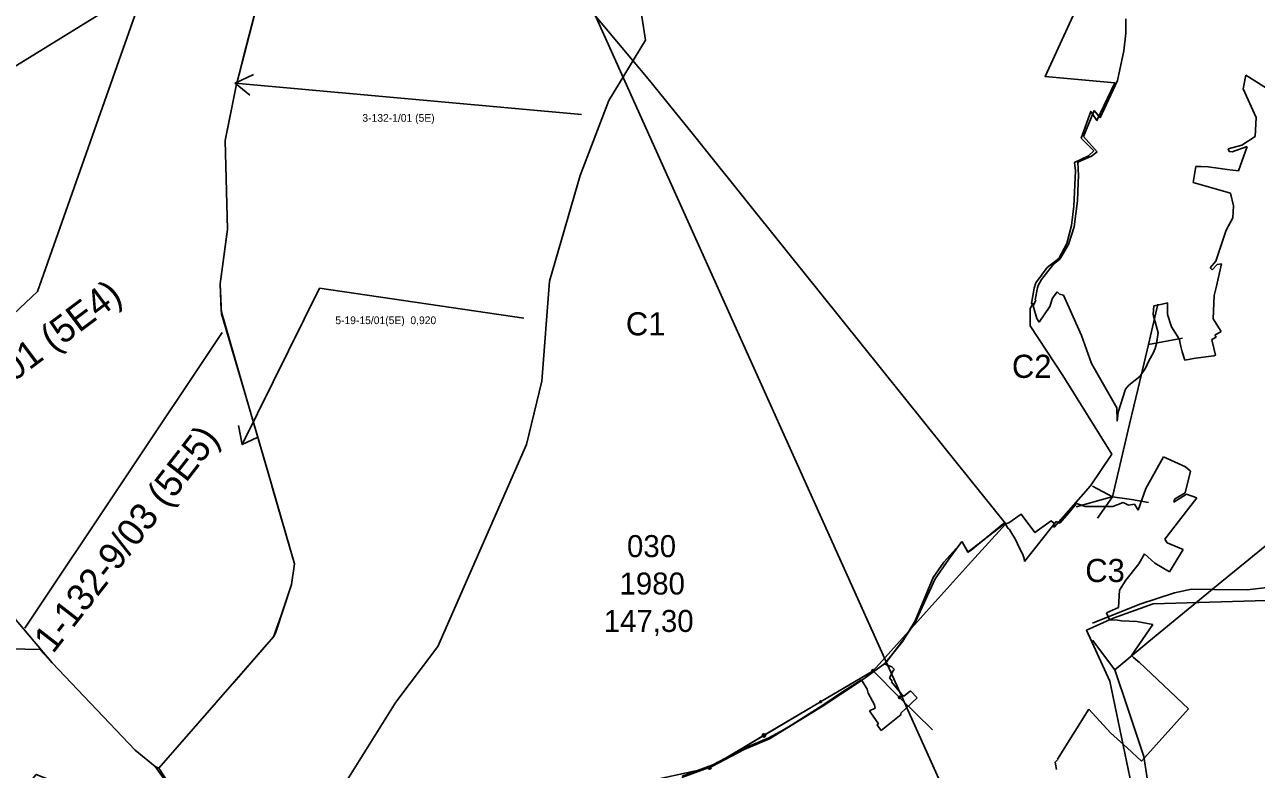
# Model space of a CAD drawing. Extents: x -557103 to -548162, y -1041918 to -1033974.
# Drawn here: x -553807 to -552210, y -1036489 to -1035524 of the extents above; entities that cross this region are included whole.
import ezdxf

# ---------------------------------------------------------------- set-up
doc = ezdxf.new("R2010")
doc.units = 0
for name, color, linetype in [('body3', 7, 'Continuous'), ('Vrstva 11', 7, 'Continuous'), ('Vrstva 12', 7, 'Continuous'), ('Vrstva 13', 7, 'Continuous'), ('Vrstva 14', 7, 'Continuous'), ('Vrstva 15', 7, 'Continuous'), ('Vrstva 16', 7, 'Continuous'), ('Vrstva 37', 7, 'Continuous'), ('Vrstva 49', 7, 'Continuous'), ('Vrstva 9', 7, 'Continuous')]:
    doc.layers.add(name, color=color, linetype=linetype)

msp = doc.modelspace()

# ---------------------------------------------------------------- linework, layer by layer
at = {"layer": 'body3'}
for p, q in [((-553499.5, -1035473.7), (-553532.1, -1035599.9)), ((-552379.3, -1035535), (-552379.4, -1035516.6)), ((-552382.1, -1035557.9), (-552379.3, -1035535)), ((-552383, -1035564), (-552382.1, -1035557.9)), ((-552390.2, -1035596.4), (-552383, -1035564)), ((-552223.9, -1035589.2), (-552227.3, -1035607.2)), ((-552104, -1035665.4), (-552223.9, -1035589.2)), ((-553533.5, -1035605.6), (-553547, -1035674)), ((-553532.1, -1035599.9), (-553533.5, -1035605.6)), ((-552412.5, -1035644.8), (-552390.2, -1035596.4)), ((-552227.3, -1035607.2), (-552210.2, -1035644.2)), ((-552434.3, -1035668.9), (-552420.3, -1035635.3)), ((-552420.3, -1035635.3), (-552412.5, -1035644.8)), ((-552210.2, -1035644.2), (-552211.4, -1035668.8)), ((-552416.5, -1035688.8), (-552434.3, -1035668.9)), ((-552211.4, -1035668.8), (-552228.7, -1035680.2)), ((-553547, -1035674), (-553544.3, -1035789.6)), ((-552228.7, -1035680.2), (-552246.5, -1035685.1)), ((-552246.5, -1035685.1), (-552245.4, -1035688.2)), ((-552241.3, -1035688.9), (-552221.9, -1035681.9)), ((-552221.9, -1035681.9), (-552233.2, -1035713.5)), ((-552441.4, -1035702.3), (-552423.9, -1035694.5)), ((-552423.9, -1035694.5), (-552416.5, -1035688.8)), ((-552245.4, -1035688.2), (-552241.3, -1035688.9)), ((-552440.8, -1035719.5), (-552441.4, -1035702.3)), ((-552288.4, -1035707.9), (-552291.9, -1035728.4)), ((-552281.9, -1035707.6), (-552288.4, -1035707.9)), ((-552272.7, -1035708.4), (-552281.9, -1035707.6)), ((-552256.8, -1035710.4), (-552272.7, -1035708.4)), ((-552247.9, -1035711.6), (-552256.8, -1035710.4)), ((-552233.2, -1035713.5), (-552247.9, -1035711.6)), ((-552441.8, -1035752.5), (-552441, -1035728.9)), ((-552441, -1035728.9), (-552440.8, -1035719.5)), ((-552291.9, -1035728.4), (-552243.6, -1035742.2)), ((-552243.6, -1035742.2), (-552239.5, -1035758.8)), ((-552446.4, -1035785.9), (-552441.8, -1035752.5)), ((-552239.5, -1035758.8), (-552240.6, -1035774.2)), ((-552240.6, -1035774.2), (-552249.1, -1035790.4)), ((-553545, -1035795.5), (-553553.5, -1035859.8)), ((-553544.3, -1035789.6), (-553545, -1035795.5)), ((-552453.8, -1035809.1), (-552446.4, -1035785.9)), ((-552249.1, -1035790.4), (-552262.8, -1035830.7)), ((-552460.9, -1035821.5), (-552453.8, -1035809.1)), ((-552472.9, -1035834.2), (-552464.7, -1035828.1)), ((-552464.7, -1035828.1), (-552460.9, -1035821.5)), ((-552488.6, -1035854.2), (-552472.9, -1035834.2)), ((-552262.8, -1035830.7), (-552270.1, -1035839.2)), ((-552270.1, -1035839.2), (-552267.3, -1035841.9)), ((-552267.3, -1035841.9), (-552261.1, -1035835)), ((-552255.1, -1035834), (-552261.8, -1035862.9)), ((-552261.1, -1035835), (-552255.1, -1035834)), ((-553553.5, -1035859.8), (-553552, -1035898.6)), ((-552493, -1035862.1), (-552488.6, -1035854.2)), ((-552497, -1035880.8), (-552493.7, -1035865.2)), ((-552493.7, -1035865.2), (-552493, -1035862.1)), ((-552468.4, -1035870.3), (-552474.3, -1035878.5)), ((-552465.4, -1035873.1), (-552468.4, -1035870.3)), ((-552460.2, -1035874.7), (-552465.4, -1035873.1)), ((-552436.8, -1035926.8), (-552460.2, -1035874.7)), ((-552264.7, -1035875.2), (-552266, -1035905.1)), ((-552261.8, -1035862.9), (-552264.7, -1035875.2)), ((-552499.6, -1035888.6), (-552496.1, -1035881)), ((-552494.6, -1035905), (-552499.6, -1035888.6)), ((-552496.1, -1035881), (-552497, -1035880.8)), ((-552477.7, -1035889.3), (-552491.7, -1035909.4)), ((-552474.3, -1035878.5), (-552477.7, -1035889.3)), ((-552343.1, -1035888.2), (-552343.8, -1035899.7)), ((-552332.2, -1035886.2), (-552343.1, -1035888.2)), ((-552325.2, -1035884.3), (-552332.2, -1035886.2)), ((-552325.2, -1035899.6), (-552325.2, -1035884.3)), ((-553552, -1035898.6), (-553519.6, -1036008.5)), ((-552491.7, -1035909.4), (-552494.6, -1035905)), ((-552343.8, -1035899.7), (-552337.5, -1035923.2)), ((-552320.1, -1035915.7), (-552325.2, -1035899.6)), ((-552266, -1035905.1), (-552255.7, -1035921.7)), ((-552337.5, -1035923.2), (-552339.4, -1035937.4)), ((-552309.9, -1035931.9), (-552320.1, -1035915.7)), ((-552255.7, -1035921.7), (-552263.7, -1035926.6)), ((-552423.8, -1035963), (-552436.8, -1035926.8)), ((-552339.4, -1035937.4), (-552341.2, -1035943.6)), ((-552309.1, -1035935.2), (-552309.9, -1035931.9)), ((-552308.1, -1035941), (-552309.1, -1035935.2)), ((-552306.1, -1035948.1), (-552308.1, -1035941)), ((-552262.3, -1035928.8), (-552268, -1035932)), ((-552268, -1035932), (-552267.3, -1035934.3)), ((-552267.3, -1035934.3), (-552263.1, -1035952.3)), ((-552263.7, -1035926.6), (-552262.3, -1035928.8)), ((-552343.7, -1035949.7), (-552349.4, -1035959.7)), ((-552341.2, -1035943.6), (-552343.7, -1035949.7)), ((-552303, -1035958.8), (-552306.1, -1035948.1)), ((-552288.8, -1035956.4), (-552303, -1035958.8)), ((-552265.2, -1035953.1), (-552288.8, -1035956.4)), ((-552263.1, -1035952.3), (-552265.2, -1035953.1)), ((-552391, -1036020.7), (-552423.8, -1035963)), ((-552353.9, -1035969.2), (-552361.1, -1035980.2)), ((-552349.4, -1035959.7), (-552353.9, -1035969.2)), ((-552361.1, -1035980.2), (-552375.3, -1035991.4)), ((-552379.9, -1035996.2), (-552389.3, -1036026.3)), ((-552375.3, -1035991.4), (-552379.9, -1035996.2)), ((-553519.6, -1036008.5), (-553487.3, -1036118.4)), ((-552390.6, -1036038), (-552391, -1036020.7)), ((-552389.3, -1036026.3), (-552390.6, -1036038)), ((-552353.2, -1036125.3), (-552330.4, -1036084.2)), ((-552330.4, -1036084.2), (-552302, -1036097.2)), ((-552302, -1036097.2), (-552295.4, -1036102.9)), ((-552295.4, -1036102.9), (-552302.4, -1036130.9)), ((-553487.3, -1036118.4), (-553485.6, -1036124.6)), ((-553485.6, -1036124.6), (-553457.3, -1036222.6)), ((-552363.4, -1036153.3), (-552353.2, -1036125.3)), ((-552317.2, -1036142.8), (-552300.6, -1036132.7)), ((-552302.4, -1036130.9), (-552316.1, -1036139.2)), ((-552300.6, -1036132.7), (-552287.3, -1036137.2)), ((-552453.4, -1036156.5), (-552445.5, -1036147.3)), ((-552445.5, -1036147.3), (-552443.1, -1036144.6)), ((-552443.1, -1036144.6), (-552431.9, -1036148.3)), ((-552431.9, -1036148.3), (-552396.1, -1036148.5)), ((-552396.1, -1036148.5), (-552382.8, -1036143.5)), ((-552382.8, -1036143.5), (-552376, -1036146.8)), ((-552376, -1036146.8), (-552368.1, -1036145.3)), ((-552368.1, -1036145.3), (-552363.4, -1036153.3)), ((-552287.3, -1036137.2), (-552328.8, -1036190.8)), ((-552316.1, -1036139.2), (-552317.2, -1036142.8)), ((-552464.7, -1036170.3), (-552453.4, -1036156.5)), ((-552579.8, -1036205.2), (-552536, -1036169.1)), ((-552536, -1036169.1), (-552534.7, -1036172.1)), ((-552534.7, -1036172.1), (-552531.7, -1036177)), ((-552531.7, -1036177), (-552531.1, -1036178)), ((-552531.1, -1036178), (-552530.5, -1036177.6)), ((-552530.5, -1036177.6), (-552528.3, -1036181.4)), ((-552510.8, -1036220), (-552469.6, -1036167.8)), ((-552469.6, -1036167.8), (-552464.7, -1036170.3)), ((-552608.7, -1036216.7), (-552591.8, -1036193.7)), ((-552591.8, -1036193.7), (-552583.8, -1036207.9)), ((-552528.3, -1036181.4), (-552522.5, -1036191.1)), ((-552522.5, -1036191.1), (-552519.8, -1036196.9)), ((-552519.8, -1036196.9), (-552512.6, -1036212.1)), ((-552328.8, -1036190.8), (-552325.6, -1036195.5)), ((-552325.6, -1036195.5), (-552304.8, -1036204.2)), ((-552583.8, -1036207.9), (-552579.8, -1036205.2)), ((-552512.6, -1036212.1), (-552511.3, -1036216.1)), ((-552355, -1036209.8), (-552362.6, -1036222.7)), ((-552341.7, -1036222), (-552355, -1036209.8)), ((-552304.8, -1036204.2), (-552322.5, -1036233)), ((-553457.3, -1036222.6), (-553461.2, -1036249.5)), ((-552626.6, -1036242.4), (-552608.7, -1036216.7)), ((-552511.3, -1036216.1), (-552510.8, -1036220)), ((-552362.6, -1036222.7), (-552379.5, -1036244.1)), ((-552322.5, -1036233), (-552341.7, -1036222)), ((-552645.8, -1036284.7), (-552626.6, -1036242.4)), ((-552379.5, -1036244.1), (-552387.4, -1036257)), ((-553461.2, -1036249.5), (-553482, -1036312.6)), ((-552387.4, -1036257), (-552388.7, -1036279.6)), ((-553771.5, -1036351), (-553831.9, -1036279.4)), ((-552651.9, -1036297.9), (-552645.8, -1036284.7)), ((-552388.7, -1036279.6), (-552404.3, -1036286.3)), ((-552404.3, -1036286.3), (-552400.4, -1036295.3)), ((-552667.4, -1036321), (-552651.9, -1036297.9)), ((-552400.4, -1036295.3), (-552390.2, -1036295.9)), ((-552390.2, -1036295.9), (-552385.1, -1036296.9)), ((-552385.1, -1036296.9), (-552365, -1036297.6)), ((-552344.4, -1036301.5), (-552371.8, -1036341.8)), ((-552365, -1036297.6), (-552344.4, -1036301.5)), ((-553484.3, -1036317.4), (-553558.7, -1036402.4)), ((-553482, -1036312.6), (-553484.3, -1036317.4)), ((-552691.9, -1036353), (-552667.4, -1036321)), ((-553664, -1036464.5), (-553771.5, -1036351)), ((-552682.8, -1036356.2), (-552691.9, -1036353)), ((-552679.3, -1036359.8), (-552682.8, -1036356.2)), ((-552371.8, -1036341.8), (-552369.4, -1036344.4)), ((-552369.4, -1036344.4), (-552363.9, -1036349)), ((-552363.9, -1036349), (-552362, -1036350.3)), ((-552362, -1036350.3), (-552298, -1036410.9)), ((-552685.9, -1036370.6), (-552680.7, -1036360.8)), ((-552682.1, -1036374.8), (-552685.9, -1036370.6)), ((-552680.7, -1036360.8), (-552679.3, -1036359.8)), ((-552772.3, -1036406.2), (-552745.3, -1036387.7)), ((-552745.3, -1036387.7), (-552722, -1036373.1)), ((-552722, -1036373.1), (-552714.6, -1036385.4)), ((-552714.6, -1036385.4), (-552713.4, -1036390.5)), ((-552683.3, -1036375.8), (-552682.1, -1036374.8)), ((-552667.6, -1036394.6), (-552683.3, -1036375.8)), ((-552658.7, -1036387.3), (-552667.6, -1036394.6)), ((-552649.8, -1036396.3), (-552658.7, -1036387.3)), ((-553558.7, -1036402.4), (-553633, -1036487.5)), ((-552713.4, -1036390.5), (-552705, -1036405.4)), ((-552671.5, -1036416.9), (-552649.8, -1036396.3)), ((-552812.3, -1036431.3), (-552772.3, -1036406.2)), ((-552704.3, -1036409.7), (-552711.8, -1036413.4)), ((-552711.8, -1036413.4), (-552709.1, -1036417.3)), ((-552709.1, -1036417.3), (-552704, -1036424.8)), ((-552705, -1036405.4), (-552704.3, -1036409.7)), ((-552683.4, -1036428.5), (-552672.7, -1036420)), ((-552672.7, -1036420), (-552670.5, -1036418.2)), ((-552670.5, -1036418.2), (-552671.5, -1036416.9)), ((-552427.2, -1036411.4), (-552467.7, -1036476.2)), ((-552399.3, -1036441.9), (-552427.2, -1036411.4)), ((-552298, -1036410.9), (-552359.1, -1036478.8)), ((-552825.5, -1036439.1), (-552818.9, -1036435.2)), ((-552818.9, -1036435.2), (-552812.3, -1036431.3)), ((-552704, -1036424.8), (-552700.2, -1036430.3)), ((-552700.2, -1036430.3), (-552702.2, -1036431.6)), ((-552702.2, -1036431.6), (-552701.4, -1036432.4)), ((-552701.4, -1036432.4), (-552699.8, -1036434)), ((-552699.8, -1036434), (-552696.4, -1036438.8)), ((-552696.4, -1036438.8), (-552683.4, -1036428.5)), ((-552873.1, -1036461.5), (-552842, -1036448.2)), ((-552842, -1036448.2), (-552832.7, -1036443.3)), ((-552832.7, -1036443.3), (-552825.5, -1036439.1)), ((-552377.4, -1036461.4), (-552399.3, -1036441.9)), ((-553638.1, -1036485.4), (-553664, -1036464.5)), ((-552914.9, -1036483.5), (-552873.1, -1036461.5)), ((-552359.1, -1036478.8), (-552377.4, -1036461.4)), ((-552954.6, -1036498.2), (-552914.9, -1036483.5)), ((-552467.4, -1036476.6), (-552471.1, -1036479.8)), ((-552471.1, -1036479.8), (-552469.1, -1036489.2)), ((-552467.7, -1036476.2), (-552467.4, -1036476.6)), ((-553633, -1036487.5), (-553638.1, -1036485.4))]:
    msp.add_line(p, q, dxfattribs=at)
at = {"layer": 'Vrstva 11'}
msp.add_line((-553534.3, -1035599.7), (-553515, -1035615.3), dxfattribs=at)
for points in [[(-553085.3, -1035640.2), (-553534.3, -1035599.7), (-553510.4, -1035588.7)], [(-553525.1, -1036068.2), (-553424.8, -1035865.7), (-553159.8, -1035904.4)], [(-553529.7, -1036043.3), (-553525.1, -1036068.2), (-553505.8, -1036059)]]:
    msp.add_lwpolyline(points, dxfattribs=at)
at = {"layer": 'Vrstva 12'}
msp.add_line((-553806.9, -1036306), (-553551.1, -1035923.1), dxfattribs=at)
msp.add_lwpolyline([(-554209.3, -1035817.9), (-553650.7, -1035473.7), (-553790.3, -1035869.7), (-554007.5, -1036074.1)], dxfattribs=at)
at = {"layer": 'Vrstva 14'}
msp.add_lwpolyline([(-551661.8, -1038633.9), (-553519.6, -1034507.2), (-553504.9, -1034676.5)], dxfattribs=at)
at = {"layer": 'Vrstva 15'}
for p, q in [((-552350.1, -1035938.3), (-552337.8, -1035886.4)), ((-552350.1, -1035938.3), (-552305.7, -1035930.2)), ((-552396.8, -1036136.1), (-552422.7, -1036122)), ((-552397.3, -1036136.1), (-552443.6, -1036148.8)), ((-552396.8, -1036136.1), (-552416.1, -1036163.5))]:
    msp.add_line(p, q, dxfattribs=at)
for points in [[(-552535.4, -1036170.7), (-552615.2, -1036071.2), (-552694.3, -1035972.7), (-552775.3, -1035871.8), (-552858.1, -1035768.8), (-552941.7, -1035664.7), (-552998.6, -1035594.1), (-553079.8, -1035497.3), (-553163.3, -1035397.2), (-553257.3, -1035282.8), (-553335.2, -1035188.3), (-553406.8, -1035101.3)], [(-552393.7, -1036360.2), (-552349.6, -1036323.5), (-552259.7, -1036249.6), (-552180, -1036184.8), (-552081.6, -1036122.4), (-551986.3, -1036061.3), (-551910.2, -1036013.3), (-551850.2, -1035917.9), (-551788.1, -1035819.1)], [(-552396.8, -1036136.1), (-552385.5, -1036088.2), (-552374.5, -1036041.9), (-552363.5, -1035994.9), (-552350.1, -1035938.3)], [(-552396.8, -1036136.1), (-552371.8, -1036139.5), (-552349.8, -1036143.4)], [(-552535.4, -1036171.2), (-552583.7, -1036224.7), (-552638.1, -1036285), (-552707.1, -1036361.3), (-552775.2, -1036401.6), (-552849.1, -1036445.3), (-552919, -1036487.2), (-553014.6, -1036507.9)], [(-552310.8, -1036764.1), (-552323.4, -1036681.2), (-552336.9, -1036596.1), (-552355.9, -1036472.4), (-552376.6, -1036410.5), (-552393.7, -1036360.2), (-552422.4, -1036321.6)]]:
    msp.add_lwpolyline(points, dxfattribs=at)
at = {"layer": 'Vrstva 16'}
msp.add_lwpolyline([(-553009.6, -1035496.7), (-553002.1, -1035544), (-553049.5, -1035622.1), (-553086.8, -1035719.3), (-553126.7, -1035856.4), (-553136.7, -1035986), (-553156.6, -1036068.2), (-553271.2, -1036329.9), (-553326, -1036402.2), (-553438.1, -1036581.7), (-553500.4, -1036678.9), (-553537.8, -1036773.6), (-553654.9, -1036898.3), (-553794.4, -1036983), (-553946.4, -1037072.7), (-554030.9, -1037138.8), (-554140.5, -1037236), (-554172.9, -1037275.9), (-554409.6, -1037435.4)], dxfattribs=at)
at = {"layer": 'Vrstva 49'}
msp.add_lwpolyline([(-553014.6, -1036507.9), (-552919.1, -1036487.2), (-552848.6, -1036445.3), (-552775.2, -1036401.6), (-552707.1, -1036361.3), (-552672.7, -1036395.9), (-552630.1, -1036437.8)], dxfattribs=at)
for centre, radius in [((-552707.1, -1036361.3), 1.52), ((-552707.1, -1036361.3), 0.585), ((-552775.2, -1036401.6), 1.08), ((-552775.2, -1036401.6), 0.612), ((-552672.7, -1036395.9), 1.36), ((-552672.7, -1036395.9), 0.795), ((-552848.6, -1036445.3), 2.17), ((-552848.6, -1036445.3), 1.13), ((-552919.1, -1036487.2), 1.96), ((-552919.1, -1036487.2), 1.09)]:
    msp.add_circle(centre, radius, dxfattribs=at)
at = {"layer": 'Vrstva 9'}
for points in [[(-552955, -1036499.8), (-552916.1, -1036485.5), (-552874.4, -1036463.6), (-552841.5, -1036449.5), (-552771.6, -1036406.9), (-552722.2, -1036374), (-552691.6, -1036352.2), (-552668.6, -1036323.2), (-552652.3, -1036296.9), (-552629.1, -1036240.5), (-552615.1, -1036220.8), (-552615.1, -1036220.8), (-552591.7, -1036194.4), (-552584.3, -1036207.5), (-552538, -1036172), (-552531.2, -1036169.5), (-552515, -1036158.6), (-552497.2, -1036182.4), (-552476.1, -1036167.1), (-552472.8, -1036169.9), (-552472.4, -1036175.4), (-552425.1, -1036121.5), (-552397.5, -1036080.7), (-552460.9, -1035978.7), (-552503.2, -1035914.2), (-552503.4, -1035892), (-552503.4, -1035892), (-552499.8, -1035885.8), (-552501.8, -1035885.4), (-552498.2, -1035865.7), (-552496, -1035858.7), (-552481.2, -1035838.5), (-552466.4, -1035827.2), (-552455.8, -1035807.7), (-552449.7, -1035784.1), (-552446.6, -1035759), (-552444.6, -1035713.5), (-552445.9, -1035702.7), (-552427.6, -1035694), (-552421, -1035687.4), (-552437.2, -1035670.9), (-552424.9, -1035636.3), (-552416.8, -1035648.3), (-552393.5, -1035599.5), (-552484.1, -1035591), (-552430.3, -1035474.1)], [(-553509.5, -1035512.6), (-553521.9, -1035560.3), (-553532.2, -1035599.9), (-553533.5, -1035605.6), (-553542, -1035648.6), (-553547, -1035674), (-553544.3, -1035789.6), (-553553.5, -1035859.8)], [(-553553.5, -1035859.8), (-553552.2, -1035894.9), (-553519.6, -1036008.5), (-553491.8, -1036103.1), (-553457.3, -1036222.6), (-553461.2, -1036249.5), (-553474.9, -1036291), (-553484.3, -1036317.4), (-553536.1, -1036376.6), (-553558.7, -1036402.5), (-553633, -1036487.5)], [(-552422.7, -1036299.6), (-552361.3, -1036275.1), (-552316.3, -1036260.2), (-552294, -1036255.5), (-552265.3, -1036255.9), (-552222.2, -1036256.5), (-552195.9, -1036253.5), (-552159.2, -1036238.6), (-552108, -1036216.6), (-552092.7, -1036213.1), (-552073.9, -1036209.4), (-551985.6, -1036206.8), (-551933.9, -1036203.5), (-551911.7, -1036200), (-551885, -1036194.9), (-551848.3, -1036184.3), (-551769.3, -1036156.4), (-551616.1, -1036101.3), (-551537.4, -1036078.2)], [(-552354.8, -1036592.7), (-552400, -1036374.7), (-552430.1, -1036308.6), (-552395.9, -1036293.4), (-552343.8, -1036274.8), (-552167.6, -1036269.4)], [(-553787.5, -1036333.8), (-553960.5, -1036330.1), (-553891.5, -1036520.6), (-553817, -1036525.2), (-553792.1, -1036495.8), (-553665.2, -1036545.5), (-553681.2, -1036641.3), (-553702.9, -1036687.9), (-553719.7, -1036719.8), (-553750.4, -1036742), (-553768.5, -1036756.7)], [(-553768.5, -1036756.7), (-553699.2, -1036764), (-553639.4, -1036761.2), (-553620.1, -1036660.9), (-553598, -1036541.2), (-553638.1, -1036485.4), (-553664, -1036464.5), (-553771.5, -1036351), (-553787.5, -1036333.8)], [(-553633, -1036487.5), (-553598, -1036541.2), (-553542.8, -1036613.2), (-553461.8, -1036565.3), (-553407.5, -1036683.2)]]:
    msp.add_lwpolyline(points, dxfattribs=at)

# ---------------------------------------------------------------- texts
at = {"layer": 'Vrstva 11'}
for s, p in [('3-132-1/01 (5E)', (-553369.2, -1035649.8)), ('5-19-15/01(5E)  0,920', (-553404.3, -1035912.1))]:
    msp.add_text(s, height=10, dxfattribs=at).set_placement(p)
at = {"layer": 'Vrstva 13'}
for s, rotation, p in [('1-132-8/01 (5E4)', 36.877, (-553961.4, -1036092.6)), ('1-132-9/03 (5E5)', 52.1322, (-553770.4, -1036340.4))]:
    msp.add_text(s, height=35, rotation=rotation, dxfattribs=at).set_placement(p)
at = {"layer": 'Vrstva 37'}
for s, p in [('C1', (-553027.6, -1035926.7)), ('C2', (-552527, -1035981.8)), ('C3', (-552431.9, -1036246.4))]:
    msp.add_text(s, height=30, dxfattribs=at).set_placement(p)
at = {"layer": 'Vrstva 9'}
for s, p in [('030', (-553026.1, -1036214.1)), ('1980', (-553035.8, -1036262.6)), ('147,30', (-553056.3, -1036311.1))]:
    msp.add_text(s, height=28.5, dxfattribs=at).set_placement(p)

doc.saveas('drawing.dxf')
